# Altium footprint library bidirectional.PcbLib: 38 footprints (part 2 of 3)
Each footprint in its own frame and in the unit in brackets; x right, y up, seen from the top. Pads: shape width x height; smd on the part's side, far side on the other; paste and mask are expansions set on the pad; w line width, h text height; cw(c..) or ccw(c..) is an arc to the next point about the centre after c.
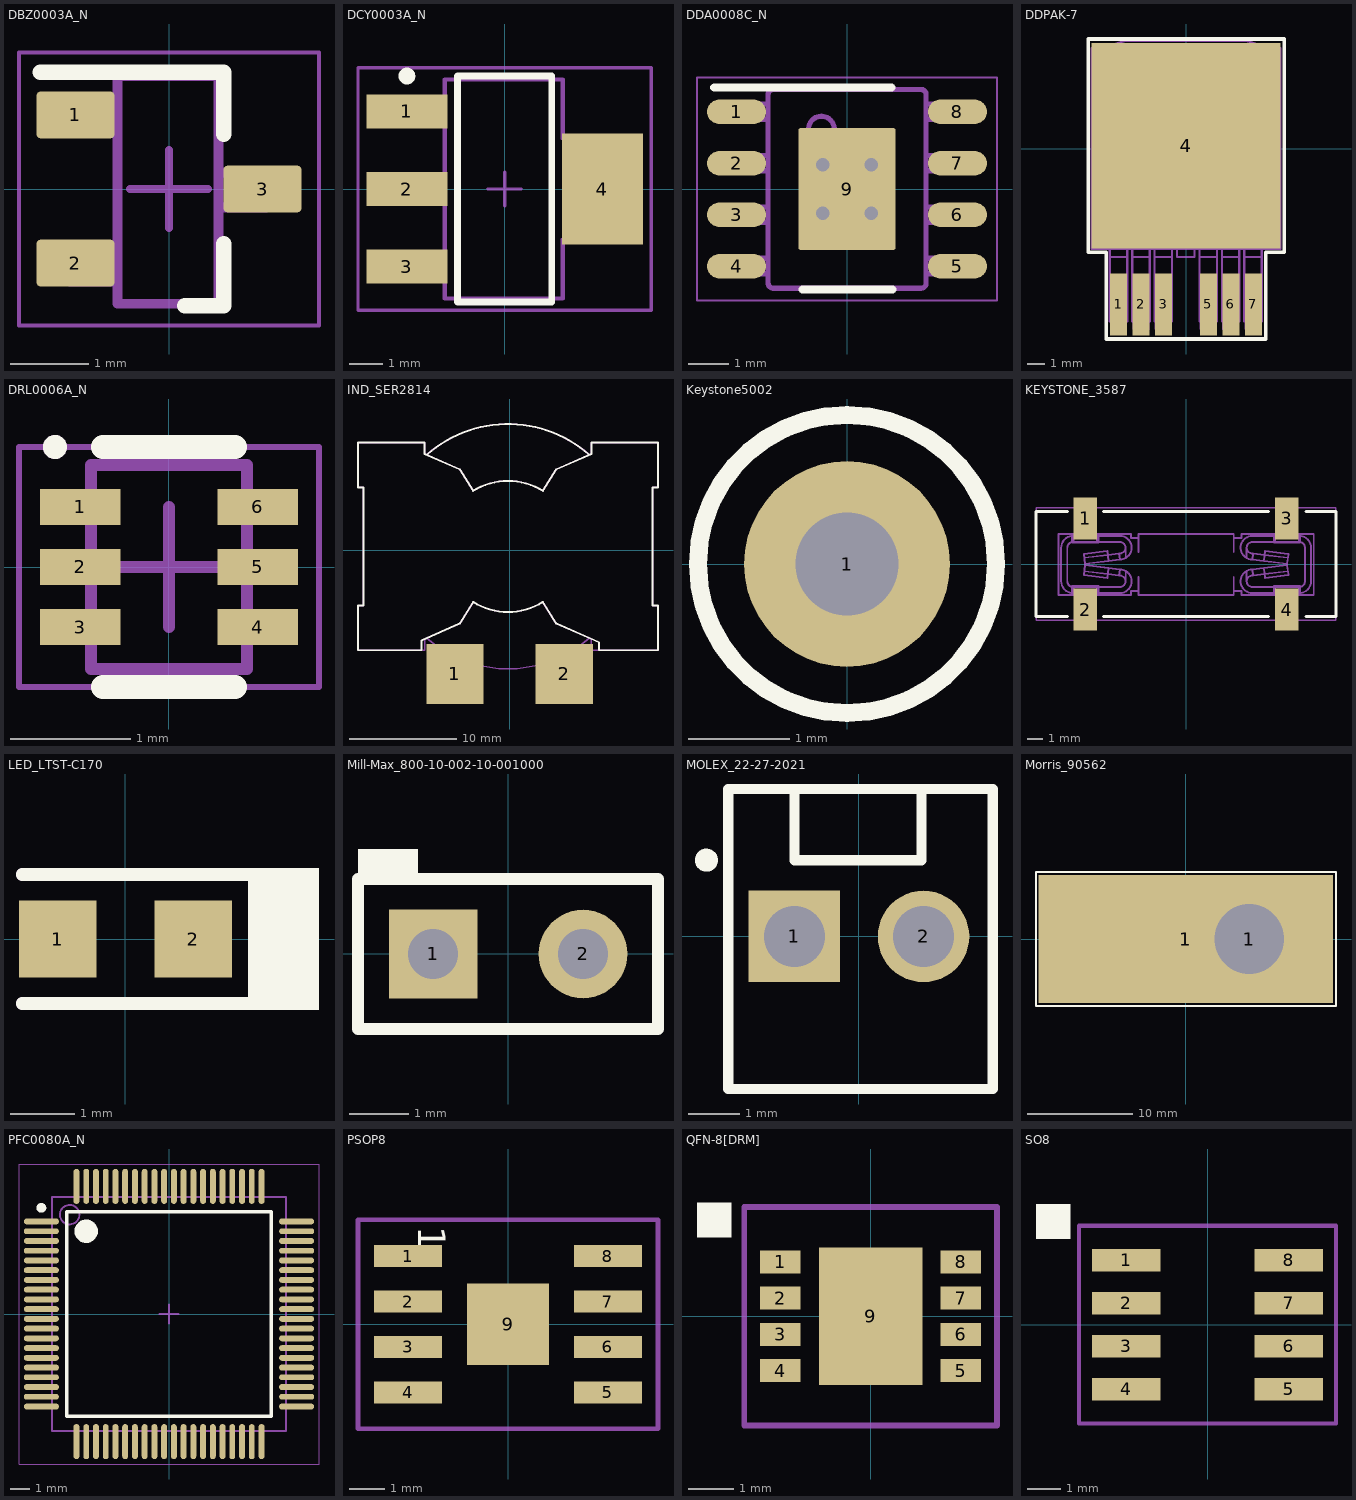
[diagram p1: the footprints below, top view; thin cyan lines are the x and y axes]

## DBZ0003A_N [mm] "SOT23, 3-Leads, Body 2.9x1.3mm, Pitch 0.95mm, Lead Span 2.4mm, IPC Medium Density"
height 1.12
pads (3):
  rrect17% 1x0.6 smd: 1(-1.2,0.95) 2(-1.2,-0.95) 3(1.2,0)
Top Overlay:
  lines w0.2: -1.651,1.5 0.7,1.5 0.7,0.7 ; 0.2,-1.5 0.7,-1.5 0.7,-0.7
Mechanical 5:
  lines w0.127: -1.27,-1.187 -1.063,-1.187 -1.005,-1.187 -0.814,-1.187 -0.66,-1.187 -0.66,-0.743 -0.814,-0.743 -1.005,-0.743 -1.063,-0.743 -1.27,-0.743 -1.27,-1.187 ; -1.27,0.718 -1.063,0.718 -1.005,0.718 -0.814,0.718 -0.66,0.718 -0.66,1.162 -0.814,1.162 -1.005,1.162 -1.063,1.162 -1.27,1.162 -1.27,0.718 ; -0.66,-1.473 0.635,-1.473 0.635,1.448 -0.66,1.448 -0.66,-1.473 ; 0.635,-0.235 0.635,0.21 0.789,0.21 0.98,0.21 1.037,0.21 1.245,0.21 1.245,-0.235 1.037,-0.235 0.98,-0.235 0.789,-0.235 0.635,-0.235
  text ".Designator" at -0.254,0.889 h0.51
Mechanical 15:
  lines w0.05: -1.925,-1.75 -1.925,1.75 1.925,1.75 1.925,-1.75 -1.925,-1.75
  lines w0.1: -0.5,0 0.5,0 ; 0,-0.5 0,0.5
3D body: height 0.98, standoff 0, extent -1.257,-1.461 1.258,1.461

## DCY0003A_N [mm] "SOT223/SC73, 4-Leads, Body 6.5x3.5mm, Pitch 2.3mm, Lead Span 7mm, IPC Medium Density"
height 1.8
pads (4):
  rect 2.4x1 smd: 1(-2.9,2.3) 2(-2.9,0) 3(-2.9,-2.3)
  rect 2.4x3.3 smd: 4(2.9,0)
Top Overlay:
  circle w0.25: c-2.9,3.35 r0.125
  lines w0.2: -1.4,-3.35 -1.4,3.35 1.4,3.35 1.4,-3.35 -1.4,-3.35
Mechanical 5:
  lines w0.127: -3.525,-2.65 -3.525,-1.95 -2.797,-1.95 -2.612,-1.95 -2.374,-1.95 -2.003,-1.95 -1.775,-1.95 -1.775,-0.35 -2.003,-0.35 -2.374,-0.35 -2.612,-0.35 -2.797,-0.35 -3.525,-0.35 -3.525,0.35 -2.797,0.35 -2.612,0.35 -2.374,0.35 -2.003,0.35 -1.775,0.35 -1.775,1.95 -2.003,1.95 -2.374,1.95 -2.612,1.95 -2.797,1.95 -3.525,1.95 -3.525,2.65 -2.797,2.65 -2.612,2.65 -2.374,2.65 -2.003,2.65 -1.775,2.65 -1.775,3.25 1.725,3.25 1.725,1.5 1.953,1.5 2.324,1.5 2.562,1.5 2.747,1.5 3.475,1.5 3.475,-1.5 2.747,-1.5 2.562,-1.5 2.324,-1.5 1.953,-1.5 1.725,-1.5 1.725,-3.25 -1.775,-3.25 -1.775,-2.65 -2.003,-2.65 -2.374,-2.65 -2.612,-2.65 -2.797,-2.65 -3.525,-2.65
  text ".Designator" at -0.425,2.5 h0.76
Mechanical 15:
  lines w0.1: -0.5,0 0.5,0 ; 0,-0.5 0,0.5 ; -4.35,-3.6 -4.35,3.6 4.35,3.6 4.35,-3.6 -4.35,-3.6
3D body: height 1.62, standoff -0.03, extent -3.5,-3.25 3.5,3.25

## DDA0008C_N [mm] "SOIC, 8-Leads, Body 4.9x3.9mm, Pitch 1.27mm, Exposed Pad, IPC Medium Density"
height 1.68
pads (9):
  rrect100% 1.45x0.6 smd: 1(-2.725,1.905) 2(-2.725,0.635) 3(-2.725,-0.635) 4(-2.725,-1.905) 5(2.725,-1.905) 6(2.725,-0.635) 7(2.725,0.635) 8(2.725,1.905)
  rrect4% 2.4x3 smd: 9(0,0)
via -0.6,-0.6 diameter 0.66 hole 0.33
via 0.6,-0.6 diameter 0.66 hole 0.33
via 0.6,0.6 diameter 0.66 hole 0.33
via -0.6,0.6 diameter 0.66 hole 0.33
Top Overlay:
  lines w0.2: -3.275,2.5 1.1,2.5 ; -1.1,-2.475 1.125,-2.475
Mechanical 5:
  lines w0.127: -1.946,-2.321 ccw(c-1.819,-2.32) -1.82,-2.447 ; -1.946,-2.321 -1.946,-2.32 -1.946,2.329 ; -1.946,2.33 -1.946,2.329 ; -1.946,2.33 cw(c-1.819,2.329) -1.82,2.456 ; -1.82,-2.447 -1.819,-2.447 ; -1.819,-2.447 1.826,-2.447 1.827,-2.447 ccw(c1.826,-2.32) 1.953,-2.321 1.953,-2.32 1.953,2.329 ; -1.819,2.456 1.826,2.456 1.827,2.456 cw(c1.826,2.329) 1.953,2.33 ; -1.82,2.456 -1.819,2.456 ; 1.953,2.329 1.953,2.33 ; -2.975,-2.091 -2.614,-2.091 -2.497,-2.091 -2.473,-2.091 -2.144,-2.091 -1.946,-2.091 -1.946,-1.71 -2.144,-1.71 -2.473,-1.71 -2.497,-1.71 -2.614,-1.71 -2.975,-1.71 -2.975,-2.091 ; -2.975,-0.821 -2.614,-0.821 -2.497,-0.821 -2.473,-0.821 -2.144,-0.821 -1.946,-0.821 -1.946,-0.44 -2.144,-0.44 -2.473,-0.44 -2.497,-0.44 -2.614,-0.44 -2.975,-0.44 -2.975,-0.821 ; -2.975,0.449 -2.614,0.449 -2.497,0.449 -2.473,0.449 -2.144,0.449 -1.946,0.449 -1.946,0.83 -2.144,0.83 -2.473,0.83 -2.497,0.83 -2.614,0.83 -2.975,0.83 -2.975,0.449 ; -2.975,1.719 -2.614,1.719 -2.497,1.719 -2.473,1.719 -2.144,1.719 -1.946,1.719 -1.946,2.1 -2.144,2.1 -2.473,2.1 -2.497,2.1 -2.614,2.1 -2.975,2.1 -2.975,1.719 ; -0.632,1.16 cw(c-0.632,1.478) -0.632,1.795 cw(c-0.632,1.478) -0.632,1.16 ; 1.953,-2.091 2.15,-2.091 2.479,-2.091 2.503,-2.091 2.621,-2.091 2.981,-2.091 2.981,-1.71 2.621,-1.71 2.503,-1.71 2.479,-1.71 2.15,-1.71 1.953,-1.71 1.953,-2.091 ; 1.953,-0.821 2.15,-0.821 2.479,-0.821 2.503,-0.821 2.621,-0.821 2.981,-0.821 2.981,-0.44 2.621,-0.44 2.503,-0.44 2.479,-0.44 2.15,-0.44 1.953,-0.44 1.953,-0.821 ; 1.953,0.449 2.15,0.449 2.479,0.449 2.503,0.449 2.621,0.449 2.981,0.449 2.981,0.83 2.621,0.83 2.503,0.83 2.479,0.83 2.15,0.83 1.953,0.83 1.953,0.449 ; 1.953,1.719 2.15,1.719 2.479,1.719 2.503,1.719 2.621,1.719 2.981,1.719 2.981,2.1 2.621,2.1 2.503,2.1 2.479,2.1 2.15,2.1 1.953,2.1 1.953,1.719
  text ".Designator" at -1.4,-0.375 h0.76
Mechanical 15:
  lines w0.05: -3.7,-2.75 3.7,-2.75 3.7,2.75 -3.7,2.75 -3.7,-2.75
  lines w0.1: -0.5,0 0.5,0 ; 0,-0.5 0,0.5
3D body: height 1.7, standoff 0, extent -3.011,-2.45 3.011,2.45

## DDPAK-7 [mil]
height 190
pads (7):
  rect 38x138 smd: 1(-150,-347) 2(-100,-347) 3(-50,-347) 5(50,-347) 6(100,-347) 7(150,-347)
  rect 420x458 smd: 4(0,6)
Top Overlay:
  lines w7.87: -217.52,-231.3 -177.17,-231.3 -177.17,-424.21 -174.21,-424.21 177.17,-424.21 177.17,-231.3 218.5,-231.3 218.5,244.09 -217.52,244.09 -217.52,-231.3
Mechanical 5:
  lines w5: -210.35,200.83 -210.35,217.23 -134.36,240.2 133.33,240.2 209.33,217.23 209.33,200.83 ; -170,-179.09 -210.55,-179.09 ; -131.02,-179.09 -120,-179.09 ; -81.02,-179.09 -70,-179.09 ; -31.02,-179.09 -20,-179.09 ; 18.98,-179.09 30,-179.09 ; 68.98,-179.09 80,-179.09 ; 118.98,-179.09 130,-179.09 ; 168.98,-179.09 209.53,-179.09 ; -210.55,-179.09 -210.55,200.83 ; -210.55,-179.09 -197.43,-165.98 ; -210.55,200.83 209.53,200.83 ; -210.55,200.83 -197.43,187.71 ; -197.43,-165.98 196.41,-165.98 ; -197.43,-165.98 -197.43,187.71 ; -197.43,187.71 196.41,187.71 ; -170,-241.3 -170,-170.9 -131.02,-170.9 -131.02,-241.3 ; -170,-241.3 -170,-264.13 -170,-299.55 -170,-307.82 -170,-385 -131.02,-385 -131.02,-307.82 -131.02,-299.55 -131.02,-264.13 -131.02,-241.3 ; -170,-241.3 -131.02,-241.3 ; -120,-241.3 -120,-170.9 -81.02,-170.9 -81.02,-241.3 ; -120,-241.3 -81.02,-241.3 ; -120,-241.3 -120,-264.13 -120,-299.55 -120,-307.82 -120,-385 -81.02,-385 -81.02,-307.82 -81.02,-299.55 -81.02,-264.13 -81.02,-241.3 ; -70,-241.3 -31.02,-241.3 ; -70,-241.3 -70,-264.13 -70,-299.55 -70,-307.82 -70,-385 -31.02,-385 -31.02,-307.82 -31.02,-299.55 -31.02,-264.13 -31.02,-241.3 ; -70,-241.3 -70,-170.9 -31.02,-170.9 -31.02,-241.3 ; 30,-241.3 30,-264.13 30,-299.55 30,-307.82 30,-385 68.98,-385 68.98,-307.82 68.98,-299.55 68.98,-264.13 68.98,-241.3 ; 30,-241.3 68.98,-241.3 ; 30,-241.3 30,-170.9 68.98,-170.9 68.98,-241.3 ; 80,-241.3 80,-264.13 80,-299.55 80,-307.82 80,-385 118.98,-385 118.98,-307.82 118.98,-299.55 118.98,-264.13 118.98,-241.3 ; 80,-241.3 80,-170.9 118.98,-170.9 118.98,-241.3 ; 80,-241.3 118.98,-241.3 ; 130,-241.3 130,-264.13 130,-299.55 130,-307.82 130,-385 168.98,-385 168.98,-307.82 168.98,-299.55 168.98,-264.13 168.98,-241.3 ; 130,-241.3 168.98,-241.3 ; 130,-241.3 130,-170.9 168.98,-170.9 168.98,-241.3 ; 196.41,-165.98 209.53,-179.09 ; 196.41,-165.98 196.41,187.71 ; 196.41,187.71 209.53,200.83 ; 209.53,-179.09 209.53,200.83 ; -20,-241.3 18.98,-241.3 18.98,-170.9 -20,-170.9 -20,-241.3
  text ".Designator" at -105,-100 h40
Mechanical 13:
  lines w0: -210,-223 210,-223 210,223 -210,223 -210,-223 ; -168,-402 -168,-223 -132,-223 -132,-402 -168,-402 ; -118,-402 -118,-223 -82,-223 -82,-402 -118,-402 ; -68,-402 -68,-223 -32,-223 -32,-402 -68,-402 ; 32,-402 32,-223 68,-223 68,-402 32,-402 ; 82,-402 82,-223 118,-223 118,-402 82,-402 ; 132,-402 132,-223 168,-223 168,-402 132,-402
  lines w6: -210,-223 210,-223 210,223 -210,223 -210,-223
3D body: height 190.16, standoff 0, extent -210.03,-385.58 210.05,239.62

## DRL0006A_N [mm] "SOTFL, 6-Flat Leads, Body 1.2x1.6x0.6mm, Pitch 0.5mm, IPC Medium Density"
height 0.6
pads (6):
  rect 0.67x0.3 smd: 1(-0.74,0.5) 2(-0.74,0) 3(-0.74,-0.5) 4(0.74,-0.5) 5(0.74,0) 6(0.74,0.5)
Top Overlay:
  circle w0.1: c-0.95,1 r0.05
  lines w0.2: -0.55,-1 0.55,-1 ; -0.55,1 0.55,1
Mechanical 5:
  circle w0.1: c-0.95,1 r0.05
  lines w0.1: -0.65,-0.85 0.65,-0.85 0.65,0.85 -0.65,0.85 -0.65,-0.85
  text ".Designator" at -0.254,0.762 h0.76
Mechanical 15:
  lines w0.05: -1.25,-1 1.25,-1 1.25,1 -1.25,1 -1.25,-1
  lines w0.1: -0.5,0 0.5,0 ; 0,-0.5 0,0.5
3D body: height 0.6, standoff 0, extent -0.65,-0.85 0.65,0.85

## IND_SER2814 [mm] "COILCRAFT"
height 14.22
pads (2):
  rect 5.33x5.59 smd: 1(-5.08,-11.505) 2(5.08,-11.505)
Top Overlay:
  lines w0.178: -7.702,8.869 cw(c-0.15,0.35) 7.402,8.869 ; -14.1,-9.3 -8.2,-9.3 -8.2,-8.388 -4.648,-6.829 -3.389,-4.819 ccw(c-0.15,0.35) 3.089,-4.819 4.348,-6.829 8.3,-8.563 8.3,-9.3 13.8,-9.3 13.8,-5.15 13.3,-5.15 13.3,5.85 13.8,5.85 13.8,10 7.6,10 7.6,8.956 4.348,7.529 3.089,5.519 ccw(c-0.15,0.35) -3.389,5.519 -4.648,7.529 -7.9,8.956 -7.9,10 -14.1,10 -14.1,5.85 -13.6,5.85 -13.6,-5.15 -14.1,-5.15 -14.1,-9.3
Mechanical 5:
  lines w0.127: -7.702,-8.169 ccw(c-0.15,0.35) 7.402,-8.169 ; -7.702,8.869 cw(c-0.15,0.35) 7.402,8.869 ; -7,-8.744 -7,-12.66 -7,-13.16 -3.2,-13.16 -3.2,-12.66 -3.2,-10.619 ; 2.9,-10.619 2.9,-12.66 2.9,-13.16 6.7,-13.16 6.7,-12.66 6.7,-8.744 ; -14.1,-9.3 -14.1,-5.15 -13.6,-5.15 -13.6,5.85 -14.1,5.85 -14.1,10 -7.9,10 -7.9,8.956 -4.648,7.529 -3.389,5.519 cw(c-0.15,0.35) 3.089,5.519 4.348,7.529 7.6,8.956 7.6,10 13.8,10 13.8,5.85 13.3,5.85 13.3,-5.15 13.8,-5.15 13.8,-9.3 7.6,-9.3 7.6,-8.256 4.348,-6.829 3.089,-4.819 cw(c-0.15,0.35) -3.389,-4.819 -4.648,-6.829 -7.9,-8.256 -7.9,-9.3 -14.1,-9.3
  text ".Designator" at -1.8,-0.6 h0.76
3D body: height 1.5, standoff 0, extent 3.201,-13.699 6.999,-9.901
3D body: height 1.5, standoff 0, extent -6.999,-13.699 -3.201,-9.901
3D body: height 12, standoff 0, extent -6.999,-9.899 -3.201,-9.401
3D body: height 12, standoff 5, extent -6.999,-9.399 -3.201,-6.801
3D body: height 12, standoff 5, extent 3.201,-9.399 6.999,-6.801
3D body: height 12, standoff 0, extent 3.201,-9.899 6.999,-9.401
3D body: height 12.64, standoff 4.56, extent -11.545,-11.045 11.245,11.745
3D body: height 14.22, standoff 0, extent -14.101,-9.301 13.801,10.001

## Keystone5002 [mil] "For Keystone 500x miniature loop terminals"
height 181.1
pads (1):
  round 80 hole 40: 1(0,0)
Top Overlay:
  circle w7: c0,0 r58
Mechanical 5:
  circle w5: c0,0 r58.31
  text ".Designator" at -45,-10 h30
3D body: height 181.97, standoff -118.11, extent -49,-49 49.04,49.23

## KEYSTONE_3587 [mm] "KEYSTONE"
height 8.25
pads (4):
  rect 1.57x2.82 smd: 1(-6.73,3.04) 2(-6.73,-3.04) 3(6.73,3.04) 4(6.73,-3.04)
Top Overlay:
  lines w0.2: -7.9,-3.5 -10,-3.5 -10,3.5 -7.9,3.5 ; -5.5,-3.5 5.5,-3.5 ; -5.5,3.5 5.5,3.5 ; 8,-3.5 10,-3.5 10,3.5 8,3.5
Mechanical 5:
  lines w0.1: -9.97,-3.75 -9.97,3.75 9.97,3.75 9.97,-3.75 -9.97,-3.75
  lines w0.127: -7.598,-2.064 -7.598,-1.48 -5.846,-1.48 -5.846,-2.064 ; -7.598,2 -7.598,1.416 -5.846,1.416 -5.846,2 ; -7.507,-1.937 -7.507,-1.531 ; -7.507,1.467 -7.507,1.873 ; -6.777,-0.481 -5.214,-0.673 -4.458,-0.766 ; -6.777,0.417 -5.214,0.609 -4.458,0.702 ; -5.932,-1.937 -5.932,-1.531 ; -5.932,1.467 -5.932,1.873 ; -3.166,-0.87 -3.166,-1.81 ; -3.166,0.806 -3.166,1.746 ; 3.184,-0.87 3.184,-1.81 ; 3.184,0.806 3.184,1.746 ; 5.864,-2.064 5.864,-1.48 7.616,-1.48 7.616,-2.064 ; 5.864,2 5.864,1.416 7.616,1.416 7.616,2 ; 5.95,-1.937 5.95,-1.531 ; 5.95,1.467 5.95,1.873 ; 6.795,-0.481 5.232,-0.673 4.476,-0.766 ; 6.795,0.417 5.232,0.609 4.476,0.702 ; 7.525,-1.937 7.525,-1.531 ; 7.525,1.467 7.525,1.873 ; -5.165,-0.269 -4.408,-0.362 ; -5.165,-0.269 -6.728,-0.077 -6.767,-0.396 -6.809,-0.736 -5.246,-0.928 -5.204,-0.588 -5.165,-0.269 ; -5.165,0.205 -4.408,0.298 ; -5.165,0.205 -6.728,0.013 -6.767,0.332 -6.809,0.672 -5.246,0.864 -5.204,0.524 -5.165,0.205 ; -4.458,-0.766 ccw(c-4.408,-0.362) -4.408,-0.769 cw(c-4.408,-1.15) -4.028,-1.175 ; -4.458,-0.766 -4.408,-0.362 ; -4.458,0.702 cw(c-4.408,0.298) -4.408,0.705 ccw(c-4.408,1.086) -4.028,1.111 ; -4.458,0.702 -4.408,0.298 ; -4.408,-0.362 cw(c-4.408,-1.15) -4.015,-0.468 ; -4.408,0.298 ccw(c-4.408,1.086) -4.015,0.404 ; -4.028,-1.175 cw(c-4.408,-1.15) -4.408,-1.531 -7.533,-1.531 cw(c-7.533,-1.15) -7.914,-1.15 -7.914,1.086 cw(c-7.533,1.086) -7.533,1.467 -4.408,1.467 cw(c-4.408,1.086) -4.028,1.111 ; -4.028,-1.175 -4.015,-1.175 -4.015,-0.468 ; -4.028,1.111 -4.015,1.111 -4.015,0.404 ; -4.015,-0.468 cw(c-4.408,-1.15) -4.408,-1.937 -7.533,-1.937 cw(c-7.533,-1.15) -8.32,-1.15 -8.32,1.086 cw(c-7.533,1.086) -7.533,1.873 -4.408,1.873 cw(c-4.408,1.086) -4.015,0.404 ; -3.166,-1.81 -3.166,-2.064 3.184,-2.064 3.184,-1.81 ; -3.166,-1.81 -3.674,-1.81 -3.674,-2.064 -8.5,-2.064 -8.5,2 -3.674,2 -3.674,1.746 -3.166,1.746 ; -3.166,1.746 -3.166,2 3.184,2 3.184,1.746 ; 3.184,-1.81 3.692,-1.81 3.692,-2.064 8.518,-2.064 8.518,2 3.692,2 3.692,1.746 3.184,1.746 ; 4.033,-0.468 ccw(c4.426,-1.15) 4.426,-1.937 7.551,-1.937 ccw(c7.551,-1.15) 8.338,-1.15 8.338,1.086 ccw(c7.551,1.086) 7.551,1.873 4.426,1.873 ccw(c4.426,1.086) 4.033,0.404 ; 4.033,-0.468 cw(c4.426,-1.15) 4.426,-0.362 ; 4.033,-0.468 4.033,-1.175 4.046,-1.175 ; 4.033,0.404 ccw(c4.426,1.086) 4.426,0.298 ; 4.033,0.404 4.033,1.111 4.046,1.111 ; 4.046,-1.175 cw(c4.426,-1.15) 4.426,-0.769 ccw(c4.426,-0.362) 4.476,-0.766 ; 4.046,-1.175 ccw(c4.426,-1.15) 4.426,-1.531 7.551,-1.531 ccw(c7.551,-1.15) 7.932,-1.15 7.932,1.086 ccw(c7.551,1.086) 7.551,1.467 4.426,1.467 ccw(c4.426,1.086) 4.046,1.111 ; 4.046,1.111 ccw(c4.426,1.086) 4.426,0.705 cw(c4.426,0.298) 4.476,0.702 ; 4.426,-0.362 5.183,-0.269 ; 4.426,-0.362 4.476,-0.766 ; 4.426,0.298 5.183,0.205 ; 4.426,0.298 4.476,0.702 ; 5.183,-0.269 5.222,-0.588 5.264,-0.928 6.827,-0.736 6.785,-0.396 6.746,-0.077 5.183,-0.269 ; 5.183,0.205 5.222,0.524 5.264,0.864 6.827,0.672 6.785,0.332 6.746,0.013 5.183,0.205
  text ".Designator" at -2.5,-0.4 h0.76
3D body: height 8.04, standoff -0.01, extent -9.9,-4.308 9.912,4.328

## LED_LTST-C170 [mm] "LITE-ON"
height 1.1
pads (2):
  rect 1.2x1.2 smd: 1(-1.05,0) 2(1.05,0)
Top Overlay:
  rectangle: 1.9,-1.1 3,1.1
  lines w0.2: -1.6,-1 2.1,-1 ; -1.6,1 2.1,1
Mechanical 5:
  rectangle: 1.9,-1.1 3,1.1
  lines w0.2: -1.6,-1 2.1,-1 ; -1.6,1 2.1,1
  text ".Designator" at -1.4,-0.4 h0.76
3D body: height 1.1, standoff 0.5, extent -0.699,-0.624 0.699,0.624
3D body: height 0.5, standoff 0, extent -1.05,-0.675 1.05,0.675

## Mill-Max_800-10-002-10-001000 [mm] "Mill-Max"
height 8.128
pads (2):
  rect 1.5x1.5 hole 0.85: 1(-1.27,0)
  round 1.5 hole 0.85: 2(1.27,0)
Top Overlay:
  rectangle: -2.541,1.27 -1.525,1.778
  lines w0.203: -2.54,-1.27 2.54,-1.27 2.54,1.27 -2.54,1.27 -2.54,-1.27
Mechanical 5:
  lines w0.102: -2.54,-1.27 -2.54,1.27 2.54,1.27 2.54,-1.27 -2.54,-1.27
  text ".Designator" at -2.032,-0.508 h0.76
3D body: height 3.17, standoff 0, extent -2.539,-1.269 2.539,1.269
3D body: height 8.13, standoff 0, extent 0.892,-0.38 1.651,0.38
3D body: height 8.13, standoff 0, extent -1.648,-0.38 -0.889,0.38
3D body: height 0.81, standoff -3, extent 0.968,-0.304 1.575,0.304
3D body: height 0.81, standoff -3, extent -1.572,-0.304 -0.965,0.304

## MOLEX_22-27-2021 [mm] "MOLEX"
height 11.75
pads (2):
  rect 1.8x1.8 hole 1.2: 1(-1.27,0)
  round 1.8 hole 1.2: 2(1.27,0)
Top Overlay:
  circle w0.254: c-3,1.5 r0.1
  lines w0.2: -1.27,2.9 -1.27,1.7 -1.27,1.5 1.23,1.5 1.23,2.9 ; -2.57,-3 2.63,-3 2.63,2.9 -2.57,2.9 -2.57,-2.4 -2.57,-3
Mechanical 5:
  lines w0.1: -1.27,2.9 -1.27,1.5 1.23,1.5 1.23,2.9 ; -2.57,-3 -2.57,2.9 2.63,2.9 2.63,-3 -2.57,-3
  text ".Designator" at -1.8,-0.5 h0.76
3D body: height 11.72, standoff -3.54, extent -2.51,-3 2.57,2.8

## Morris_90562 [mil] "Morris"
height 450
pads (2):
  rect 1100x480 smd: 1(0,0)
  round 350 hole 260: 1(237,0)
Top Overlay:
  lines w8: -560,-250 -505,-250 561,-251 561,-241 561,251 523,251 -560,251 -560,229 -560,-250
Mechanical 5:
  circle w5: c240,0 r135
  circle w5: c-311.61,15.98 r125
  lines w5: -326.61,-109.02 -326.61,140.98 ; -296.61,-109.02 -296.61,140.98 ; -50,-209.99 -50,220 ; -535,-225 535,-225 535,225 -535,225 -535,-225
  text ".Designator" at 125,-15 h30
3D body: height 443.94, standoff 0, extent -542.5,-225 532.5,225

## PFC0080A_N [mm] "Thin QFP, 80-Leads, Body 12x12mm, Pitch 0.5mm, IPC Medium Density"
height 1.2
pads (80):
  oval 1.8x0.3 smd: 1(-6.55,4.75) 2(-6.55,4.25) 3(-6.55,3.75) 4(-6.55,3.25) 5(-6.55,2.75) 6(-6.55,2.25) 7(-6.55,1.75) 8(-6.55,1.25) 9(-6.55,0.75) 10(-6.55,0.25) 11(-6.55,-0.25) 12(-6.55,-0.75) 13(-6.55,-1.25) 14(-6.55,-1.75) 15(-6.55,-2.25) 16(-6.55,-2.75) 17(-6.55,-3.25) 18(-6.55,-3.75) 19(-6.55,-4.25) 20(-6.55,-4.75) 41(6.55,-4.75) 42(6.55,-4.25) 43(6.55,-3.75) 44(6.55,-3.25) 45(6.55,-2.75) 46(6.55,-2.25) 47(6.55,-1.75) 48(6.55,-1.25) 49(6.55,-0.75) 50(6.55,-0.25) 51(6.55,0.25) 52(6.55,0.75) 53(6.55,1.25) 54(6.55,1.75) 55(6.55,2.25) 56(6.55,2.75) 57(6.55,3.25) 58(6.55,3.75) 59(6.55,4.25) 60(6.55,4.75)
  oval 0.3x1.8 smd: 21(-4.75,-6.55) 22(-4.25,-6.55) 23(-3.75,-6.55) 24(-3.25,-6.55) 25(-2.75,-6.55) 26(-2.25,-6.55) 27(-1.75,-6.55) 28(-1.25,-6.55) 29(-0.75,-6.55) 30(-0.25,-6.55) 31(0.25,-6.55) 32(0.75,-6.55) 33(1.25,-6.55) 34(1.75,-6.55) 35(2.25,-6.55) 36(2.75,-6.55) 37(3.25,-6.55) 38(3.75,-6.55) 39(4.25,-6.55) 40(4.75,-6.55) 61(4.75,6.55) 62(4.25,6.55) 63(3.75,6.55) 64(3.25,6.55) 65(2.75,6.55) 66(2.25,6.55) 67(1.75,6.55) 68(1.25,6.55) 69(0.75,6.55) 70(0.25,6.55) 71(-0.25,6.55) 72(-0.75,6.55) 73(-1.25,6.55) 74(-1.75,6.55) 75(-2.25,6.55) 76(-2.75,6.55) 77(-3.25,6.55) 78(-3.75,6.55) 79(-4.25,6.55) 80(-4.75,6.55)
Top Overlay:
  circle w0.25: c-6.55,5.45 r0.125
  circle w0.6: c-4.25,4.25 r0.3
  lines w0.2: -5.25,-5.25 -5.25,5.25 5.25,5.25 5.25,-5.25 -5.25,-5.25
Mechanical 5:
  circle w0.1: c-5.1,5.1 r0.5
  lines w0.1: -6,-6 -6,6 6,6 6,-6 -6,-6
  text ".Designator" at -1.854,-0.508 h0.76
Mechanical 15:
  lines w0.05: -7.7,-7.7 -7.7,7.7 7.7,7.7 7.7,-7.7 -7.7,-7.7
  lines w0.1: -0.5,0 0.5,0 ; 0,-0.5 0,0.5
3D body: height 1.2, standoff 0, extent -6,-6 6,6

## PSOP8 [mil]
pads (9):
  rect 75x24 smd: 1(-110,75) 2(-110,25) 3(-110,-25) 4(-110,-75) 5(110,-75) 6(110,-25) 7(110,25) 8(110,75)
  rect 90x90 smd: 9(0,0)
Top Overlay:
  text "1" at -99,107.57 h30
Mechanical 5:
  lines w5: -165,-115 165,-115 165,115 -165,115 -165,-115
  text "*" at -89,107.57 h30
  text ".Designator" at -73,-20 h30

## QFN-8[DRM] [mil]
pads (9):
  rect 35x20 smd: 1(-78.5,47.2) 2(-78.5,15.7) 3(-78.5,-15.8) 4(-78.5,-47.3) 5(78.5,-47.3) 6(78.5,-15.8) 7(78.5,15.7) 8(78.5,47.2)
  rect 90x120 smd: 9(0,0)
Top Overlay:
  region: -151,98.9 -151,68.9 -121,68.9 -121,98.9
Mechanical 5:
  lines w5: -110,-95 110,-95 110,95 -110,95 -110,-95
  text "*" at -110,80 h30
  text ".Designator" at -73,-20 h30

## SO8 [mil]
pads (8):
  rect 80x26 smd: 1(-95,75) 2(-95,25) 3(-95,-25) 4(-95,-75) 5(94,-75) 6(94,-25) 7(94,25) 8(94,75)
Top Overlay:
  region: -160,100 -160,140 -200,140 -200,100
Mechanical 5:
  lines w5: -150,-115 -150,115 149,115 149,-115 -150,-115
  text "*" at -55.9,51.4 h30
  text ".Designator" at -60,-20 h30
